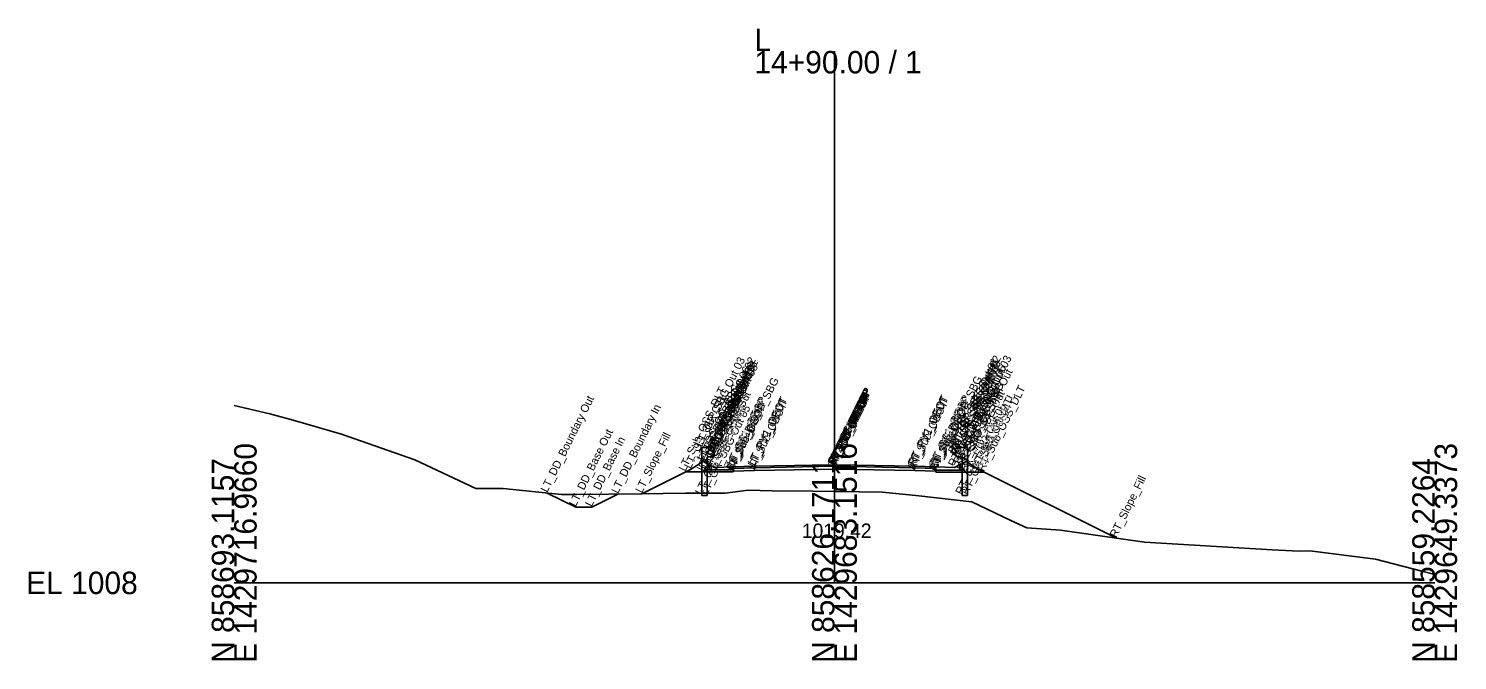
# Model space of a CAD drawing. Extents: x -26 to 2303, y -10 to 19558.
# Drawn here: x 2124.3 to 2302.8, y 1490.3 to 1569.3 of the extents above; entities that cross this region are included whole.
import ezdxf

# ---------------------------------------------------------------- set-up
doc = ezdxf.new("R2010")
doc.units = 0
for name, color, linetype in [('Default', 7, 'Continuous'), ('Exist Cross Section Cell', 7, 'Continuous'), ('Exist XS Center Line Elevation Label', 7, 'Continuous'), ('Exist XS Ground Line', 7, 'Continuous'), ('Prop CMT Conc Surface', 7, 'Continuous'), ('Prop CMT Concrete Structures', 7, 'Continuous'), ('Prop CMT Ditch DDE', 7, 'Continuous'), ('Prop CMT Guardrail SBG', 7, 'Continuous'), ('Prop CMT Pvmt Course 1', 7, 'Continuous'), ('Prop CMT Pvmt Course 2', 7, 'Continuous'), ('Prop CMT Pvmt Course SBG', 7, 'Continuous'), ('Prop CMT Pvmt Surface', 7, 'Continuous'), ('Prop CMT Pvmt Surface Shoulder', 7, 'Continuous'), ('Prop CMT Shld Paved Course 1', 7, 'Continuous'), ('Prop CMT Shld Paved Course 2', 7, 'Continuous'), ('Prop CMT Slope Grass', 7, 'Continuous'), ('Prop CMT Subgrade Earthwork', 7, 'Continuous'), ('Prop XS Dump Level', 7, 'Continuous')]:
    doc.layers.add(name, color=color, linetype=linetype)

msp = doc.modelspace()

# ---------------------------------------------------------------- linework, layer by layer
at = {"layer": 'Exist Cross Section Cell'}
for p, q in [((2225, 1500), (2225, 1566.48)), ((2150, 1500), (2225, 1500)), ((2225, 1500), (2300, 1500))]:
    msp.add_line(p, q, dxfattribs=at)
at = {"layer": 'Exist XS Ground Line'}
msp.add_lwpolyline([(2150, 1522.16), (2154.44, 1521.11), (2157.38, 1520.32), (2163.41, 1518.57), (2172.59, 1515.4), (2180.19, 1511.79), (2183.59, 1511.8), (2190.91, 1511.04), (2192.75, 1511.05), (2200.81, 1511.15), (2206.39, 1511.22), (2206.72, 1511.22), (2211.34, 1511.22), (2214.22, 1511.58), (2217.21, 1511.5), (2222.29, 1511.46), (2225, 1511.42), (2228.08, 1511.38), (2231, 1511.35), (2235.17, 1510.92), (2242.15, 1510.13), (2247.04, 1507.78), (2249.02, 1506.88), (2253.23, 1506.61), (2263.73, 1505.07), (2279.71, 1504.14), (2283.07, 1503.95), (2284.38, 1504.01), (2292.62, 1502.95), (2298.41, 1501.45), (2300, 1501.06)], dxfattribs=at)
at = {"layer": 'Prop CMT Conc Surface'}
for points in [[(2212.36, 1514.52), (2210.03, 1514.43), (2209.36, 1514.77)], [(2237.68, 1514.52), (2240.02, 1514.43), (2240.68, 1514.77)]]:
    msp.add_lwpolyline(points, dxfattribs=at)
at = {"layer": 'Prop CMT Concrete Structures'}
for points in [[(2212.36, 1514.52), (2210.03, 1514.43), (2209.36, 1514.77)], [(2209.36, 1514.77), (2209.36, 1514.11)], [(2209.36, 1514.11), (2212.36, 1514.11)], [(2212.36, 1514.11), (2212.36, 1514.52)], [(2237.68, 1514.52), (2240.02, 1514.43), (2240.68, 1514.77)], [(2237.68, 1514.1), (2237.68, 1514.52)], [(2240.68, 1514.1), (2237.68, 1514.1)], [(2240.68, 1514.77), (2240.68, 1514.1)]]:
    msp.add_lwpolyline(points, dxfattribs=at)
at = {"layer": 'Prop CMT Ditch DDE'}
msp.add_lwpolyline([(2200.95, 1511.15), (2197.95, 1511.09), (2194.67, 1509.45), (2192.67, 1509.45), (2189.11, 1511.23)], dxfattribs=at)
at = {"layer": 'Prop CMT Guardrail SBG'}
for points in [[(2208.42, 1510.93), (2208.42, 1516.93)], [(2208.42, 1516.93), (2209.76, 1516.93), (2210.03, 1516.64)], [(2210.03, 1516.05), (2209.76, 1515.76), (2209.09, 1515.76)], [(2209.09, 1515.76), (2209.09, 1510.93)], [(2210.03, 1516.64), (2209.76, 1516.35)], [(2209.76, 1516.35), (2210.03, 1516.05)], [(2241.62, 1516.93), (2240.29, 1516.93), (2240.02, 1516.64)], [(2240.02, 1516.64), (2240.29, 1516.34)], [(2240.29, 1516.34), (2240.02, 1516.05)], [(2240.02, 1516.05), (2240.29, 1515.76), (2240.95, 1515.76)], [(2240.95, 1515.76), (2240.95, 1510.93)], [(2241.62, 1510.93), (2241.62, 1516.93)], [(2209.09, 1510.93), (2208.42, 1510.93)], [(2240.95, 1510.93), (2241.62, 1510.93)]]:
    msp.add_lwpolyline(points, dxfattribs=at)
at = {"layer": 'Prop CMT Pvmt Course 1'}
for points in [[(2225, 1514.77), (2215, 1514.57)], [(2215, 1514.57), (2215, 1514.37)], [(2215, 1514.37), (2225, 1514.57)], [(2225, 1514.57), (2225, 1514.77)], [(2225, 1514.77), (2235, 1514.57)], [(2225, 1514.57), (2225, 1514.77)], [(2235, 1514.37), (2225, 1514.57)], [(2235, 1514.57), (2235, 1514.37)]]:
    msp.add_lwpolyline(points, dxfattribs=at)
msp.add_lwpolyline([(2225, 1514.57), (2225, 1514.65), (2225, 1514.65), (2225, 1514.57)], close=True, dxfattribs=at)
msp.add_lwpolyline([(2225, 1514.57), (2225, 1514.65), (2225, 1514.65), (2225, 1514.57)], close=True, dxfattribs=at)
at = {"layer": 'Prop CMT Pvmt Course 2'}
for points in [[(2225, 1514.57), (2215, 1514.37)], [(2215, 1514.37), (2215, 1514.03)], [(2215, 1514.03), (2225, 1514.23)], [(2225, 1514.23), (2225, 1514.57)], [(2225, 1514.23), (2225, 1514.57)], [(2225, 1514.57), (2235, 1514.37)], [(2235, 1514.03), (2225, 1514.23)], [(2235, 1514.37), (2235, 1514.03)]]:
    msp.add_lwpolyline(points, dxfattribs=at)
at = {"layer": 'Prop CMT Pvmt Course SBG'}
for points in [[(2212.36, 1514.11), (2209.36, 1514.11), (2208.86, 1514.11), (2208.61, 1513.86)], [(2212.36, 1513.86), (2212.36, 1514.11)], [(2237.68, 1513.85), (2237.68, 1514.1)], [(2237.68, 1514.1), (2240.68, 1514.1), (2241.18, 1514.1), (2241.43, 1513.85)], [(2208.61, 1513.86), (2212.36, 1513.86)], [(2241.43, 1513.85), (2237.68, 1513.85)]]:
    msp.add_lwpolyline(points, dxfattribs=at)
at = {"layer": 'Prop CMT Pvmt Surface'}
for points in [[(2225, 1514.77), (2215, 1514.57)], [(2225, 1514.77), (2235, 1514.57)]]:
    msp.add_lwpolyline(points, dxfattribs=at)
at = {"layer": 'Prop CMT Pvmt Surface Shoulder'}
for points in [[(2215, 1514.57), (2212.36, 1514.52)], [(2235, 1514.57), (2237.68, 1514.52)]]:
    msp.add_lwpolyline(points, dxfattribs=at)
at = {"layer": 'Prop CMT Shld Paved Course 1'}
for points in [[(2215, 1514.57), (2212.36, 1514.52)], [(2212.36, 1514.52), (2212.36, 1514.31)], [(2212.36, 1514.31), (2215, 1514.37)], [(2215, 1514.37), (2215, 1514.57)], [(2235, 1514.57), (2237.68, 1514.52)], [(2235, 1514.37), (2235, 1514.57)], [(2237.68, 1514.31), (2235, 1514.37)], [(2237.68, 1514.52), (2237.68, 1514.31)]]:
    msp.add_lwpolyline(points, dxfattribs=at)
at = {"layer": 'Prop CMT Shld Paved Course 2'}
for points in [[(2215, 1514.37), (2212.36, 1514.31)], [(2212.36, 1514.31), (2212.36, 1514.11), (2212.36, 1513.98)], [(2212.36, 1513.98), (2215, 1514.03)], [(2215, 1514.03), (2215, 1514.37)], [(2235, 1514.37), (2237.68, 1514.31)], [(2235, 1514.03), (2235, 1514.37)], [(2237.68, 1513.98), (2235, 1514.03)], [(2237.68, 1514.31), (2237.68, 1514.1), (2237.68, 1513.98)]]:
    msp.add_lwpolyline(points, dxfattribs=at)
at = {"layer": 'Prop CMT Slope Grass'}
for points in [[(2209.36, 1514.77), (2208.59, 1515.17), (2207.03, 1514.19), (2200.95, 1511.15)], [(2240.68, 1514.77), (2241.45, 1515.17), (2243.02, 1514.19), (2260.23, 1505.58)]]:
    msp.add_lwpolyline(points, dxfattribs=at)
at = {"layer": 'Prop CMT Subgrade Earthwork'}
for points in [[(2215, 1514.03), (2212.36, 1513.98)], [(2212.36, 1513.98), (2212.36, 1513.86)], [(2225, 1514.23), (2215, 1514.03)], [(2225, 1514.23), (2235, 1514.03)], [(2235, 1514.03), (2237.68, 1513.98)], [(2237.68, 1513.98), (2237.68, 1513.85)], [(2212.36, 1513.86), (2208.61, 1513.86), (2206.36, 1513.86)], [(2237.68, 1513.85), (2241.43, 1513.85), (2243.68, 1513.85)]]:
    msp.add_lwpolyline(points, dxfattribs=at)

# ---------------------------------------------------------------- texts
at = {"layer": 'Default'}
msp.add_text('-', height=0.0001, dxfattribs=at).set_placement((2150, 1500))
at = {"layer": 'Exist Cross Section Cell'}
for s, p in [('L', (2215, 1566.48)), ('14+90.00 / 1', (2215, 1563.68)), ('EL 1008', (2124, 1498.6))]:
    msp.add_text(s, height=2.8, dxfattribs=at).set_placement(p)
for s, p in [('E 1429716.9660', (2152.8, 1490)), ('E 1429683.1516', (2227.8, 1490)), ('E 1429649.3373', (2302.8, 1490)), ('N 858693.1157', (2150, 1490)), ('N 858626.1711', (2225, 1490)), ('N 858559.2264', (2300, 1490))]:
    msp.add_text(s, height=2.8, rotation=90, dxfattribs=at).set_placement(p)
at = {"layer": 'Exist XS Center Line Elevation Label'}
msp.add_text('1019.42', height=1.8, dxfattribs=at).set_placement((2220.93, 1505.62))
at = {"layer": 'Prop XS Dump Level'}
for s, p in [('RT_GR_SBG Out 02', (2240.29, 1516.93)), ('RT_GR_SBG Out 03', (2241.62, 1516.93)), ('LT_GR_SBG Out 03', (2208.42, 1516.93)), ('LT_SBG_C1 Shelf Out', (2208.86, 1514.11)), ('LT_GR_SBG Out 06', (2209.09, 1515.76)), ('LT_GR_SBG Out 02', (2209.76, 1516.93)), ('LT_GR_SBG Out 09', (2209.76, 1516.35)), ('LT_GR_SBG Out 07', (2209.76, 1515.76)), ('LT_GR_SBG Out 01', (2210.03, 1516.64)), ('LT_GR_SBG Out 08', (2210.03, 1516.05)), ('RT_GR_SBG Out 01', (2240.02, 1516.64)), ('RT_GR_SBG Out 08', (2240.02, 1516.05)), ('RT_GR_SBG Out 09', (2240.29, 1516.34)), ('RT_GR_SBG Out 07', (2240.29, 1515.76)), ('RT_GR_SBG Out 06', (2240.95, 1515.76)), ('RT_SBG_C1 Shelf Out', (2241.18, 1514.1)), ('LT_GS_OS_SBG', (2208.59, 1515.17)), ('LT_CG_Top_BOC', (2209.36, 1514.77)), ('LT_Sub_OEOP_SBG', (2212.36, 1513.86)), ('RT_Sub_OEOP_SBG', (2237.68, 1513.85)), ('RT_CG_Top_BOC', (2240.68, 1514.77)), ('RT_GS_OS_SBG', (2241.45, 1515.17)), ('RT_Sub_OSS_DLT', (2243.68, 1513.85)), ('LT_DD_Boundary Out', (2189.11, 1511.23)), ('LT_Sub_OSS_DLT', (2206.36, 1513.86)), ('LT_GS_OS_CTL', (2207.03, 1514.19)), ('LT_Sub_SBG Out', (2208.61, 1513.86)), ('LT_CG_Bot_BOC', (2209.36, 1514.11)), ('LT_CG_Top_Gut', (2210.03, 1514.43)), ('LT_PS1_OEOP', (2212.36, 1514.52)), ('LT_PS2_OEOP', (2212.36, 1514.31)), ('LT_PV1_OEOT', (2215, 1514.57)), ('LT_PV2_OEOT', (2215, 1514.37)), ('RT_PV1_OEEOP', (2225, 1514.65)), ('RT_PV2_OEEOP', (2225, 1514.57)), ('LT_PV1_OEEOP', (2225, 1514.65)), ('LT_PV2_OEEOP', (2225, 1514.57)), ('RT_Sub_OEEOP', (2225, 1514.23)), ('RT_PV1_IEEOP', (2225, 1514.65)), ('RT_PV2_IEEOP', (2225, 1514.57)), ('LT_Sub_OEEOP', (2225, 1514.23)), ('LT_PV1_IEEOP', (2225, 1514.65)), ('LT_PV2_IEEOP', (2225, 1514.57)), ('RT_PV1_OEOT', (2235, 1514.57)), ('RT_PV2_OEOT', (2235, 1514.37)), ('RT_Sub_OEOT', (2235, 1514.03)), ('RT_PS1_OEOP', (2237.68, 1514.52)), ('RT_PS2_OEOP', (2237.68, 1514.31)), ('RT_CG_Top_Gut', (2240.02, 1514.43)), ('RT_CG_Bot_BOC', (2240.68, 1514.1)), ('RT_Sub_SBG Out', (2241.43, 1513.85)), ('RT_GS_OS_CTL', (2243.02, 1514.19)), ('LT_DD_Boundary In', (2197.95, 1511.09)), ('LT_GR_SBG Out 04', (2208.42, 1510.93)), ('LT_GR_SBG Out 05', (2209.09, 1510.93)), ('LT_Sub_OEOP', (2212.36, 1513.98)), ('LT_CG_Bot_IE', (2212.36, 1514.11)), ('LT_Sub_OEOT', (2215, 1514.03)), ('RT_Sub_OEOP', (2237.68, 1513.98)), ('RT_CG_Bot_IE', (2237.68, 1514.1)), ('RT_GR_SBG Out 05', (2240.95, 1510.93)), ('RT_GR_SBG Out 04', (2241.62, 1510.93)), ('PV1_PGL', (2225, 1514.77)), ('PV2_PGL', (2225, 1514.57)), ('LT_DD_Base Out', (2192.67, 1509.45)), ('LT_DD_Base In', (2194.67, 1509.45)), ('LT_Slope_Fill', (2200.95, 1511.15)), ('RT_Slope_Fill', (2260.23, 1505.58))]:
    msp.add_text(s, height=1, rotation=63.5833, dxfattribs=at).set_placement(p)

doc.saveas('drawing.dxf')
